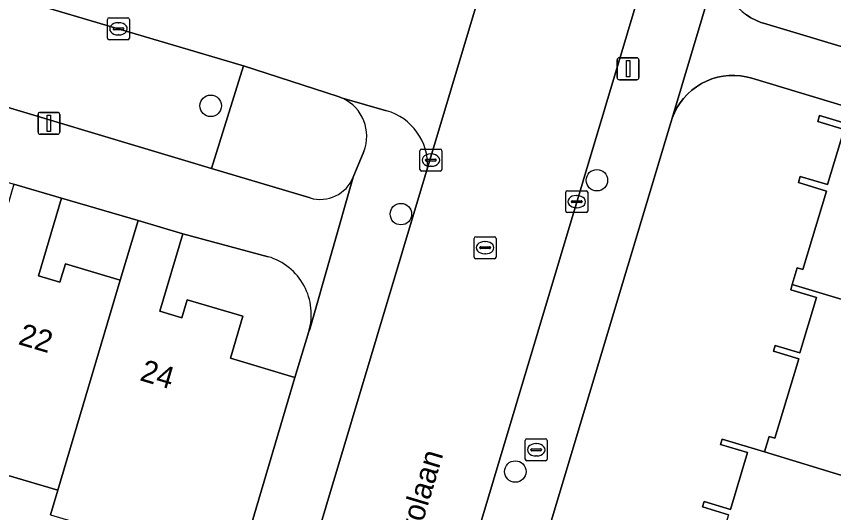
# Model space of a CAD drawing. Extents: x 162184 to 163154, y 385507 to 386516.
# Drawn here: x 162691.57 to 162728.79, y 386180.64 to 386203.25 of the extents above; entities that cross this region are included whole.
import ezdxf

# ---------------------------------------------------------------- set-up
doc = ezdxf.new("R2010")
doc.units = 0
for name, color, linetype in [('IMGEO_Boom', 7, 'Continuous'), ('IMGEO_Brandkraan', 7, 'Continuous'), ('IMGEO_Erf', 7, 'Continuous'), ('IMGEO_Groenvoorziening', 7, 'Continuous'), ('IMGEO_Kolk', 7, 'Continuous'), ('IMGEO_Lichtmast', 7, 'Continuous'), ('IMGEO_Openbare_ruimte_label', 7, 'Continuous'), ('IMGEO_Pand', 7, 'Continuous'), ('IMGEO_Pand_nummerreeks', 7, 'Continuous'), ('IMGEO_Rijbaan_lokaal_open', 7, 'Continuous'), ('IMGEO_Rioolput', 7, 'Continuous'), ('IMGEO_Voetpad_open', 7, 'Continuous')]:
    doc.layers.add(name, color=color, linetype=linetype)

msp = doc.modelspace()

# ---------------------------------------------------------------- linework, layer by layer
at = {"layer": 'IMGEO_Boom'}
for centre in [(162700.42, 386199.175), (162718.008, 386195.786), (162709.082, 386194.242), (162714.292, 386182.518)]:
    msp.add_circle(centre, 0.489, dxfattribs=at)
at = {"layer": 'IMGEO_Brandkraan'}
for p, q in [((162714.743, 386183.083), (162714.743, 386183.935)), ((162714.818, 386184.009), (162715.67, 386184.009)), ((162715.231, 386183.789), (162715.256, 386183.789)), ((162715.744, 386183.935), (162715.744, 386183.083)), ((162715.002, 386183.503), (162715.002, 386183.515)), ((162715.44, 386183.466), (162715.042, 386183.466)), ((162715.045, 386183.552), (162715.443, 386183.552)), ((162715.486, 386183.515), (162715.486, 386183.503)), ((162715.67, 386183.009), (162714.818, 386183.009)), ((162715.254, 386183.229), (162715.229, 386183.229))]:
    msp.add_line(p, q, dxfattribs=at)
for points in [[(162714.743, 386183.083), (162714.743, 386183.935)], [(162714.818, 386184.009), (162715.67, 386184.009)], [(162715.744, 386183.935), (162715.744, 386183.083)], [(162715.67, 386183.009), (162714.818, 386183.009)]]:
    msp.add_lwpolyline(points, dxfattribs=at)
for centre, radius, start, end in [((162714.82, 386183.933), 0.0765, 91.552, 178.448), ((162714.82, 386183.933), 0.0765, 91.552, 178.448), ((162715.668, 386183.933), 0.0765, 1.552, 88.448), ((162715.668, 386183.933), 0.0765, 1.552, 88.448), ((162715.042, 386183.512), 0.0403, 85.8775, 175.7526), ((162715.039, 386183.502), 0.0366, 178.938, 274.7102), ((162715.443, 386183.509), 0.043, 264.8664, 352.4533), ((162715.447, 386183.514), 0.0386, 1.7309, 96.639), ((162714.82, 386183.085), 0.0765, 181.552, 268.448), ((162714.82, 386183.085), 0.0765, 181.552, 268.448), ((162715.668, 386183.085), 0.0765, 271.552, 358.448), ((162715.668, 386183.085), 0.0765, 271.552, 358.448)]:
    msp.add_arc(centre, radius, start, end, dxfattribs=at)
for centre, major_axis, ratio, start_param, end_param in [((162715.23, 386183.509), (-0.387, 0.002), 0.722429, 4.712389, 7.853982), ((162715.255, 386183.509), (-0.39, 0.002), 0.717154, 1.570796, 4.712389)]:
    msp.add_ellipse(centre, major_axis=major_axis, ratio=ratio, start_param=start_param, end_param=end_param, dxfattribs=at)
at = {"layer": 'IMGEO_Erf'}
for points in [[(162728.84, 386223.351), (162723.746, 386206.383), (162723.685, 386206.143), (162723.647, 386205.898), (162723.63, 386205.651), (162723.635, 386205.403), (162723.662, 386205.157), (162723.712, 386204.914), (162723.782, 386204.677), (162723.874, 386204.447), (162723.986, 386204.226), (162724.117, 386204.016), (162724.267, 386203.818), (162724.433, 386203.635), (162724.615, 386203.467), (162724.812, 386203.316), (162725.021, 386203.183), (162725.241, 386203.07), (162725.47, 386202.977), (162725.6, 386202.934), (162745.202, 386197.049)], [(162745.506, 386194.259), (162725.062, 386200.438), (162724.806, 386200.503), (162724.546, 386200.544), (162724.283, 386200.563), (162724.019, 386200.557), (162723.757, 386200.529), (162723.499, 386200.476), (162723.246, 386200.401), (162723.001, 386200.304), (162722.766, 386200.185), (162722.542, 386200.046), (162722.331, 386199.887), (162722.136, 386199.71), (162721.957, 386199.516), (162721.796, 386199.308), (162721.654, 386199.085), (162721.533, 386198.851), (162721.434, 386198.607), (162721.387, 386198.465), (162705.654, 386146.025)], [(162724.003, 386180.547), (162722.812, 386180.905), (162722.885, 386181.146), (162724.089, 386180.784), (162724.871, 386183.382), (162723.642, 386183.752), (162723.717, 386183.999), (162725.644, 386183.419), (162725.853, 386184.111), (162726.108, 386184.034), (162727.199, 386187.657), (162726.052, 386188.002), (162726.129, 386188.258), (162727.25, 386187.92), (162728.01, 386190.443), (162726.831, 386190.797), (162726.905, 386191.043), (162727.133, 386191.799), (162727.383, 386191.723), (162728.458, 386195.292), (162727.182, 386195.676), (162727.268, 386195.962), (162728.512, 386195.587), (162729.269, 386198.103), (162728.06, 386198.467), (162728.142, 386198.74), (162740.665, 386194.969)], [(162703.039, 386192.3), (162699.149, 386193.349), (162698.103, 386189.822), (162699.111, 386189.523), (162699.355, 386190.342), (162701.887, 386189.591), (162701.319, 386187.678), (162704.256, 386186.807), (162704.89, 386188.895)], [(162693.133, 386180.547), (162693.464, 386181.665), (162691.204, 386182.336), (162691.132, 386182.093), (162688.131, 386182.984), (162687.918, 386182.267), (162687.686, 386182.336), (162687.034, 386180.211), (162681.466, 386181.862), (162682.092, 386183.975), (162682.375, 386184.93), (162676.996, 386186.36), (162676.773, 386185.611), (162676.533, 386185.682), (162671.213, 386187.169), (162670.97, 386187.241), (162670.543, 386185.797), (162664.983, 386187.492)]]:
    msp.add_lwpolyline(points, dxfattribs=at)
msp.add_lwpolyline([(162693.622, 386194.963), (162692.573, 386191.429), (162693.557, 386191.137), (162693.806, 386191.976), (162696.305, 386191.235), (162697.111, 386193.953)], close=True, dxfattribs=at)
msp.add_arc((162702.263, 386189.673), 2.74, 343.5122, 73.5459, dxfattribs=at)
at = {"layer": 'IMGEO_Groenvoorziening'}
msp.add_lwpolyline([(162700.454, 386196.325), (162701.908, 386200.996), (162701.811, 386201.027), (162689.472, 386204.679), (162688.104, 386200.024)], close=True, dxfattribs=at)
for points in [[(162706.424, 386199.519), (162706.224, 386199.597), (162701.908, 386200.996), (162700.454, 386196.325), (162704.943, 386194.981)], [(162706.911, 386195.922), (162707.388, 386197.091)]]:
    msp.add_lwpolyline(points, dxfattribs=at)
for centre, radius, start, end in [((162705.636, 386197.801), 1.89, 337.948, 65.3616), ((162705.408, 386196.537), 1.624, 253.3531, 337.7565)]:
    msp.add_arc(centre, radius, start, end, dxfattribs=at)
at = {"layer": 'IMGEO_Kolk'}
for p, q in [((162695.721, 386202.256), (162695.721, 386203.108)), ((162695.796, 386203.182), (162696.648, 386203.182)), ((162696.722, 386203.108), (162696.722, 386202.256)), ((162696.209, 386202.962), (162696.234, 386202.962)), ((162695.98, 386202.676), (162695.98, 386202.688)), ((162696.418, 386202.639), (162696.02, 386202.639)), ((162696.023, 386202.725), (162696.421, 386202.725)), ((162696.232, 386202.402), (162696.207, 386202.402)), ((162696.464, 386202.688), (162696.464, 386202.676)), ((162696.648, 386202.182), (162695.796, 386202.182)), ((162710.022, 386197.202), (162710.874, 386197.202)), ((162709.947, 386196.276), (162709.947, 386197.128)), ((162710.435, 386196.982), (162710.46, 386196.982)), ((162710.948, 386197.128), (162710.948, 386196.276)), ((162710.206, 386196.696), (162710.206, 386196.708)), ((162710.644, 386196.659), (162710.246, 386196.659)), ((162710.249, 386196.745), (162710.647, 386196.745)), ((162710.458, 386196.422), (162710.433, 386196.422)), ((162710.69, 386196.708), (162710.69, 386196.696)), ((162710.874, 386196.202), (162710.022, 386196.202)), ((162716.661, 386195.31), (162717.513, 386195.31)), ((162716.586, 386194.384), (162716.586, 386195.236)), ((162717.074, 386195.09), (162717.099, 386195.09)), ((162717.587, 386195.236), (162717.587, 386194.384)), ((162716.845, 386194.804), (162716.845, 386194.816)), ((162717.283, 386194.767), (162716.885, 386194.767)), ((162716.888, 386194.853), (162717.286, 386194.853)), ((162717.329, 386194.816), (162717.329, 386194.804)), ((162717.513, 386194.31), (162716.661, 386194.31)), ((162717.097, 386194.53), (162717.072, 386194.53))]:
    msp.add_line(p, q, dxfattribs=at)
for points in [[(162695.721, 386202.256), (162695.721, 386203.108)], [(162695.796, 386203.182), (162696.648, 386203.182)], [(162696.722, 386203.108), (162696.722, 386202.256)], [(162696.648, 386202.182), (162695.796, 386202.182)], [(162710.022, 386197.202), (162710.874, 386197.202)], [(162709.947, 386196.276), (162709.947, 386197.128)], [(162710.948, 386197.128), (162710.948, 386196.276)], [(162710.874, 386196.202), (162710.022, 386196.202)], [(162716.661, 386195.31), (162717.513, 386195.31)], [(162716.586, 386194.384), (162716.586, 386195.236)], [(162717.587, 386195.236), (162717.587, 386194.384)], [(162717.513, 386194.31), (162716.661, 386194.31)]]:
    msp.add_lwpolyline(points, dxfattribs=at)
for centre, radius, start, end in [((162695.798, 386203.106), 0.0765, 91.552, 178.448), ((162695.798, 386203.106), 0.0765, 91.552, 178.448), ((162696.646, 386203.106), 0.0765, 1.552, 88.448), ((162696.646, 386203.106), 0.0765, 1.552, 88.448), ((162696.02, 386202.685), 0.0403, 85.8775, 175.7526), ((162696.017, 386202.675), 0.0366, 178.938, 274.7102), ((162696.421, 386202.682), 0.043, 264.8664, 352.4533), ((162696.425, 386202.687), 0.0386, 1.7309, 96.639), ((162695.798, 386202.258), 0.0765, 181.552, 268.448), ((162695.798, 386202.258), 0.0765, 181.552, 268.448), ((162696.646, 386202.258), 0.0765, 271.552, 358.448), ((162696.646, 386202.258), 0.0765, 271.552, 358.448), ((162710.024, 386197.126), 0.0765, 91.552, 178.448), ((162710.024, 386197.126), 0.0765, 91.552, 178.448), ((162710.872, 386197.126), 0.0765, 1.552, 88.448), ((162710.872, 386197.126), 0.0765, 1.552, 88.448), ((162710.246, 386196.705), 0.0403, 85.8775, 175.7526), ((162710.243, 386196.695), 0.0366, 178.938, 274.7102), ((162710.647, 386196.702), 0.043, 264.8664, 352.4533), ((162710.651, 386196.707), 0.0386, 1.7309, 96.639), ((162710.024, 386196.278), 0.0765, 181.552, 268.448), ((162710.024, 386196.278), 0.0765, 181.552, 268.448), ((162710.872, 386196.278), 0.0765, 271.552, 358.448), ((162710.872, 386196.278), 0.0765, 271.552, 358.448), ((162716.663, 386195.234), 0.0765, 91.552, 178.448), ((162716.663, 386195.234), 0.0765, 91.552, 178.448), ((162717.511, 386195.234), 0.0765, 1.552, 88.448), ((162717.511, 386195.234), 0.0765, 1.552, 88.448), ((162716.885, 386194.813), 0.0403, 85.8775, 175.7526), ((162716.882, 386194.803), 0.0366, 178.938, 274.7102), ((162717.286, 386194.81), 0.043, 264.8664, 352.4533), ((162717.29, 386194.815), 0.0386, 1.7309, 96.639), ((162716.663, 386194.386), 0.0765, 181.552, 268.448), ((162716.663, 386194.386), 0.0765, 181.552, 268.448), ((162717.511, 386194.386), 0.0765, 271.552, 358.448), ((162717.511, 386194.386), 0.0765, 271.552, 358.448)]:
    msp.add_arc(centre, radius, start, end, dxfattribs=at)
for centre, major_axis, ratio, start_param, end_param in [((162696.208, 386202.682), (-0.387, 0.002), 0.722429, 4.712389, 7.853982), ((162696.233, 386202.682), (-0.39, 0.002), 0.717154, 1.570796, 4.712389), ((162710.434, 386196.702), (-0.387, 0.002), 0.722429, 4.712389, 7.853982), ((162710.459, 386196.702), (-0.39, 0.002), 0.717154, 1.570796, 4.712389), ((162717.073, 386194.81), (-0.387, 0.002), 0.722429, 4.712389, 7.853982), ((162717.098, 386194.81), (-0.39, 0.002), 0.717154, 1.570796, 4.712389)]:
    msp.add_ellipse(centre, major_axis=major_axis, ratio=ratio, start_param=start_param, end_param=end_param, dxfattribs=at)
at = {"layer": 'IMGEO_Lichtmast'}
for p, q in [((162718.929, 386200.465), (162718.929, 386201.265)), ((162718.929, 386201.265), (162718.929, 386200.465)), ((162719.029, 386201.365), (162719.819, 386201.365)), ((162719.819, 386201.365), (162719.029, 386201.365)), ((162719.919, 386201.265), (162719.919, 386200.465)), ((162719.919, 386200.465), (162719.919, 386201.265)), ((162719.819, 386200.365), (162719.029, 386200.365)), ((162719.029, 386200.365), (162719.819, 386200.365)), ((162692.557, 386197.978), (162692.557, 386198.778)), ((162692.557, 386198.778), (162692.557, 386197.978)), ((162692.657, 386198.878), (162693.447, 386198.878)), ((162693.447, 386198.878), (162692.657, 386198.878)), ((162693.547, 386198.778), (162693.547, 386197.978)), ((162693.547, 386197.978), (162693.547, 386198.778)), ((162693.447, 386197.878), (162692.657, 386197.878)), ((162692.657, 386197.878), (162693.447, 386197.878))]:
    msp.add_line(p, q, dxfattribs=at)
for points in [[(162719.349, 386201.24), (162719.499, 386201.24), (162719.499, 386200.49), (162719.349, 386200.49), (162719.349, 386201.24)], [(162692.977, 386198.753), (162693.127, 386198.753), (162693.127, 386198.003), (162692.977, 386198.003), (162692.977, 386198.753)]]:
    msp.add_lwpolyline(points, dxfattribs=at)
for centre, start, end in [((162719.029, 386201.265), 90, 180), ((162719.029, 386201.265), 90, 180), ((162719.819, 386201.265), 0, 90), ((162719.819, 386201.265), 360, 90), ((162719.029, 386200.465), 180, 270), ((162719.029, 386200.465), 180, 270), ((162719.819, 386200.465), 270, 0), ((162719.819, 386200.465), 270, 0), ((162692.657, 386198.778), 90, 180), ((162692.657, 386198.778), 90, 180), ((162693.447, 386198.778), 0, 90), ((162693.447, 386198.778), 360, 90), ((162692.657, 386197.978), 180, 270), ((162692.657, 386197.978), 180, 270), ((162693.447, 386197.978), 270, 0), ((162693.447, 386197.978), 270, 0)]:
    msp.add_arc(centre, 0.1, start, end, dxfattribs=at)
at = {"layer": 'IMGEO_Pand'}
for points in [[(162740.665, 386194.969), (162728.142, 386198.74), (162728.06, 386198.467), (162729.269, 386198.103), (162728.512, 386195.587), (162727.268, 386195.962), (162727.182, 386195.676), (162728.458, 386195.292), (162727.383, 386191.723), (162727.133, 386191.799), (162726.905, 386191.043), (162735.195, 386188.551), (162739.422, 386187.278), (162741.658, 386194.67)], [(162691.463, 386195.604), (162690.669, 386192.933), (162687.686, 386182.336), (162687.918, 386182.267), (162688.131, 386182.984), (162691.132, 386182.093), (162691.204, 386182.336), (162693.464, 386181.665), (162696.305, 386191.235), (162693.806, 386191.976), (162693.557, 386191.137), (162692.573, 386191.429), (162693.622, 386194.963)], [(162704.256, 386186.807), (162701.319, 386187.678), (162701.887, 386189.591), (162699.355, 386190.342), (162699.111, 386189.523), (162698.103, 386189.822), (162699.149, 386193.349), (162697.111, 386193.953), (162696.305, 386191.235), (162693.464, 386181.665), (162693.133, 386180.547), (162697.373, 386179.289), (162696.812, 386177.398), (162701.088, 386176.13)], [(162733.932, 386180.882), (162735.535, 386186.208), (162738.805, 386185.229), (162739.422, 386187.278), (162735.195, 386188.551), (162726.905, 386191.043), (162726.831, 386190.797), (162728.01, 386190.443), (162727.25, 386187.92), (162726.129, 386188.258), (162726.052, 386188.002), (162727.199, 386187.657), (162726.108, 386184.034), (162725.853, 386184.111), (162725.644, 386183.419)], [(162725.644, 386183.419), (162723.717, 386183.999), (162723.642, 386183.752), (162724.871, 386183.382), (162724.089, 386180.784), (162722.885, 386181.146), (162722.812, 386180.905), (162724.003, 386180.547), (162722.921, 386176.955), (162722.718, 386177.017), (162722.473, 386176.205), (162730.718, 386173.725), (162732.336, 386179.099), (162735.589, 386178.119), (162736.214, 386180.195), (162733.932, 386180.882)]]:
    msp.add_lwpolyline(points, close=True, dxfattribs=at)
at = {"layer": 'IMGEO_Rijbaan_lokaal_open'}
for points in [[(162729.19, 386259.752), (162728.39, 386256.734), (162726.379, 386250), (162719.4, 386226.716), (162710.296, 386196.346), (162684.842, 386111.426), (162691.517, 386109.426), (162697.472, 386129.304), (162699.069, 386134.636), (162733.627, 386250)], [(162710.296, 386196.346), (162719.4, 386226.716)], [(162684.836, 386206.051), (162689.472, 386204.679), (162701.811, 386201.027), (162701.908, 386200.996), (162706.224, 386199.597), (162706.424, 386199.519), (162708.42, 386198.954)]]:
    msp.add_lwpolyline(points, dxfattribs=at)
msp.add_arc((162707.716, 386196.469), 2.583, 357.2688, 74.188, dxfattribs=at)
at = {"layer": 'IMGEO_Rioolput'}
for p, q in [((162712.416, 386192.287), (162712.416, 386193.139)), ((162712.491, 386193.213), (162713.343, 386193.213)), ((162713.417, 386193.139), (162713.417, 386192.287)), ((162712.675, 386192.707), (162712.675, 386192.719)), ((162712.718, 386192.756), (162713.116, 386192.756)), ((162712.904, 386192.993), (162712.929, 386192.993)), ((162713.159, 386192.719), (162713.159, 386192.707)), ((162713.113, 386192.67), (162712.715, 386192.67)), ((162712.927, 386192.433), (162712.902, 386192.433)), ((162713.343, 386192.213), (162712.491, 386192.213))]:
    msp.add_line(p, q, dxfattribs=at)
for points in [[(162712.416, 386192.287), (162712.416, 386193.139)], [(162712.491, 386193.213), (162713.343, 386193.213)], [(162713.417, 386193.139), (162713.417, 386192.287)], [(162713.343, 386192.213), (162712.491, 386192.213)]]:
    msp.add_lwpolyline(points, dxfattribs=at)
for centre, radius, start, end in [((162712.493, 386193.137), 0.0765, 91.552, 178.448), ((162712.493, 386193.137), 0.0765, 91.552, 178.448), ((162713.341, 386193.137), 0.0765, 1.552, 88.448), ((162713.341, 386193.137), 0.0765, 1.552, 88.448), ((162712.715, 386192.716), 0.0403, 85.8775, 175.7526), ((162712.712, 386192.706), 0.0366, 178.938, 274.7102), ((162713.116, 386192.713), 0.043, 264.8664, 352.4533), ((162713.12, 386192.718), 0.0386, 1.7309, 96.639), ((162712.493, 386192.289), 0.0765, 181.552, 268.448), ((162712.493, 386192.289), 0.0765, 181.552, 268.448), ((162713.341, 386192.289), 0.0765, 271.552, 358.448), ((162713.341, 386192.289), 0.0765, 271.552, 358.448)]:
    msp.add_arc(centre, radius, start, end, dxfattribs=at)
for centre, major_axis, ratio, start_param, end_param in [((162712.903, 386192.713), (-0.387, 0.002), 0.722429, 4.712389, 7.853982), ((162712.928, 386192.713), (-0.39, 0.002), 0.717154, 1.570796, 4.712389)]:
    msp.add_ellipse(centre, major_axis=major_axis, ratio=ratio, start_param=start_param, end_param=end_param, dxfattribs=at)
at = {"layer": 'IMGEO_Voetpad_open'}
msp.add_lwpolyline([(162721.387, 386198.465), (162721.434, 386198.607), (162723.685, 386206.143), (162723.746, 386206.383), (162728.84, 386223.351), (162728.866, 386223.475), (162730.951, 386230.401), (162730.989, 386230.496), (162735.341, 386245.037), (162736.826, 386250), (162733.627, 386250), (162699.069, 386134.636), (162699.516, 386134.501), (162701.942, 386133.579), (162703.362, 386138.221), (162703.404, 386138.39), (162703.662, 386139.272), (162703.7, 386139.388), (162705.601, 386145.815), (162705.654, 386146.025)], close=True, dxfattribs=at)
for points in [[(162704.943, 386194.981), (162700.454, 386196.325), (162688.104, 386200.024), (162683.454, 386201.416), (162683.339, 386201.439), (162677.098, 386203.344), (162676.868, 386203.433), (162668.123, 386206.04), (162651.146, 386211.101)], [(162723.685, 386206.143), (162721.434, 386198.607), (162721.533, 386198.851), (162721.654, 386199.085), (162721.796, 386199.308), (162721.957, 386199.516), (162722.136, 386199.71), (162722.331, 386199.887), (162722.542, 386200.046), (162722.766, 386200.185), (162723.001, 386200.304), (162723.246, 386200.401), (162723.499, 386200.476), (162723.757, 386200.529), (162724.019, 386200.557), (162724.283, 386200.563), (162724.546, 386200.544), (162724.806, 386200.503), (162725.062, 386200.438), (162745.506, 386194.259)], [(162665.894, 386203.459), (162669.313, 386202.384), (162671.463, 386201.746), (162674.98, 386200.654), (162677.007, 386200.053), (162680.375, 386199.002), (162682.52, 386198.365), (162685.957, 386197.294), (162688.098, 386196.659), (162691.463, 386195.604), (162693.622, 386194.963), (162697.111, 386193.953), (162699.149, 386193.349), (162703.039, 386192.3)], [(162745.202, 386197.049), (162725.6, 386202.934), (162725.47, 386202.977), (162725.241, 386203.07), (162725.021, 386203.183), (162724.812, 386203.316)], [(162708.42, 386198.954), (162706.424, 386199.519)], [(162707.388, 386197.091), (162706.911, 386195.922), (162704.932, 386188.998), (162704.89, 386188.895), (162704.256, 386186.807), (162701.088, 386176.13), (162699.811, 386171.795), (162699.756, 386171.624), (162697.274, 386163.359), (162697.211, 386163.095), (162682.002, 386112.374), (162681.973, 386107.91)], [(162684.842, 386111.426), (162710.296, 386196.346)], [(162704.89, 386188.895), (162704.932, 386188.998), (162706.911, 386195.922)]]:
    msp.add_lwpolyline(points, dxfattribs=at)
for centre, radius, start, end in [((162705.636, 386197.801), 1.89, 337.948, 65.3616), ((162707.716, 386196.469), 2.583, 357.2688, 74.188), ((162705.408, 386196.537), 1.624, 253.3531, 337.7565), ((162702.263, 386189.673), 2.74, 343.5122, 73.5459)]:
    msp.add_arc(centre, radius, start, end, dxfattribs=at)

# ---------------------------------------------------------------- texts
at = {"layer": 'IMGEO_Openbare_ruimte_label'}
msp.add_text('Eratolaan', height=1, rotation=73.2678, dxfattribs=at).set_placement((162709.374, 386177.836))
at = {"layer": 'IMGEO_Pand_nummerreeks'}
for s, p in [('22', (162691.614, 386188.328)), ('24', (162697.15, 386186.684))]:
    msp.add_text(s, height=1, rotation=343.4539, dxfattribs=at).set_placement(p)

doc.saveas('drawing.dxf')
